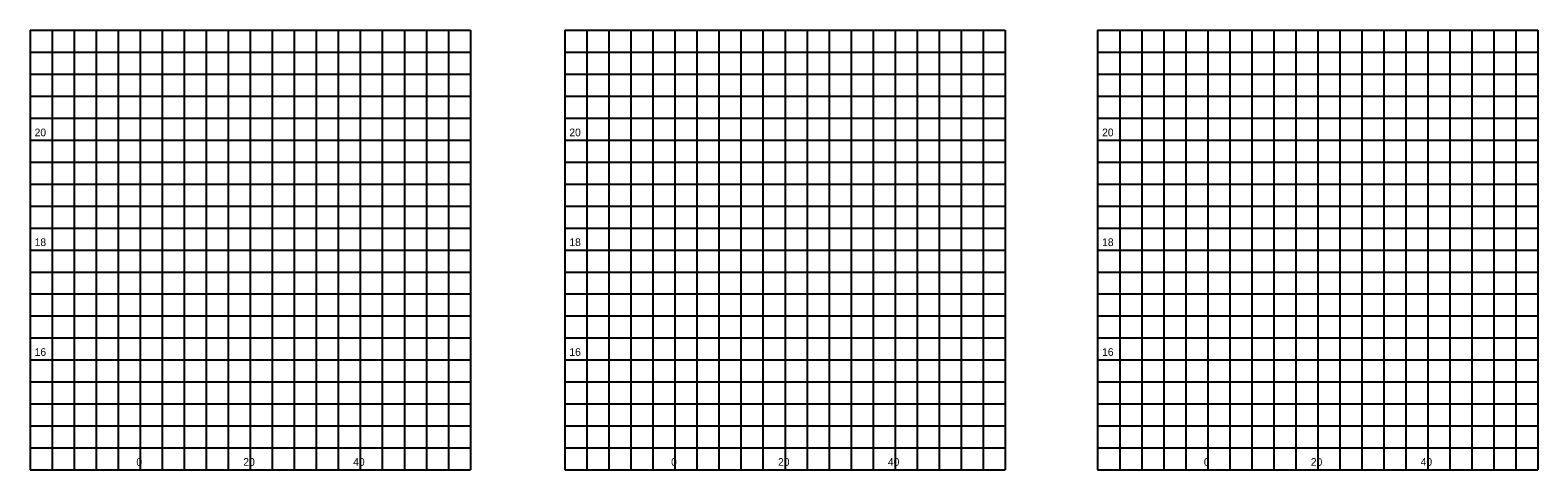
# Model space of a CAD drawing. Extents: x 127723 to 128378, y 21426 to 23736.
# Drawn here: x 127739.5 to 128013.5, y 21910.9 to 21990.9 of the extents above; entities that cross this region are included whole.
import ezdxf

# ---------------------------------------------------------------- set-up
doc = ezdxf.new("R2010")
doc.units = 0
for name, color, linetype in [('GroundCover', 7, 'Continuous'), ('Miscellaneous0', 7, 'Continuous'), ('SheetBorder_dp', 7, 'Continuous')]:
    doc.layers.add(name, color=color, linetype=linetype)

msp = doc.modelspace()

# ---------------------------------------------------------------- linework, layer by layer
at = {"layer": 'Miscellaneous0'}
for p, q in [((127743.54, 21990.89), (127743.54, 21910.89)), ((127747.54, 21990.89), (127747.54, 21910.89)), ((127751.54, 21990.89), (127751.54, 21910.89)), ((127755.54, 21990.89), (127755.54, 21910.89)), ((127763.54, 21990.89), (127763.54, 21910.89)), ((127767.54, 21990.89), (127767.54, 21910.89)), ((127771.54, 21990.89), (127771.54, 21910.89)), ((127775.54, 21990.89), (127775.54, 21910.89)), ((127783.54, 21990.89), (127783.54, 21910.89)), ((127787.54, 21990.89), (127787.54, 21910.89)), ((127791.54, 21990.89), (127791.54, 21910.89)), ((127795.54, 21990.89), (127795.54, 21910.89)), ((127803.54, 21990.89), (127803.54, 21910.89)), ((127807.54, 21990.89), (127807.54, 21910.89)), ((127811.54, 21990.89), (127811.54, 21910.89)), ((127815.54, 21990.89), (127815.54, 21910.89)), ((127840.72, 21990.89), (127840.72, 21910.89)), ((127844.72, 21990.89), (127844.72, 21910.89)), ((127848.72, 21990.89), (127848.72, 21910.89)), ((127852.72, 21990.89), (127852.72, 21910.89)), ((127860.72, 21990.89), (127860.72, 21910.89)), ((127864.72, 21990.89), (127864.72, 21910.89)), ((127868.72, 21990.89), (127868.72, 21910.89)), ((127872.72, 21990.89), (127872.72, 21910.89)), ((127880.72, 21990.89), (127880.72, 21910.89)), ((127884.72, 21990.89), (127884.72, 21910.89)), ((127888.72, 21990.89), (127888.72, 21910.89)), ((127892.72, 21990.89), (127892.72, 21910.89)), ((127900.72, 21990.89), (127900.72, 21910.89)), ((127904.72, 21990.89), (127904.72, 21910.89)), ((127908.72, 21990.89), (127908.72, 21910.89)), ((127912.72, 21990.89), (127912.72, 21910.89)), ((127937.54, 21990.89), (127937.54, 21910.89)), ((127941.54, 21990.89), (127941.54, 21910.89)), ((127945.54, 21990.89), (127945.54, 21910.89)), ((127949.54, 21990.89), (127949.54, 21910.89)), ((127957.54, 21990.89), (127957.54, 21910.89)), ((127961.54, 21990.89), (127961.54, 21910.89)), ((127965.54, 21990.89), (127965.54, 21910.89)), ((127969.54, 21990.89), (127969.54, 21910.89)), ((127977.54, 21990.89), (127977.54, 21910.89)), ((127981.54, 21990.89), (127981.54, 21910.89)), ((127985.54, 21990.89), (127985.54, 21910.89)), ((127989.54, 21990.89), (127989.54, 21910.89)), ((127997.54, 21990.89), (127997.54, 21910.89)), ((128001.54, 21990.89), (128001.54, 21910.89)), ((128005.54, 21990.89), (128005.54, 21910.89)), ((128009.54, 21990.89), (128009.54, 21910.89)), ((127739.54, 21986.89), (127819.54, 21986.89)), ((127836.72, 21986.89), (127916.72, 21986.89)), ((127933.54, 21986.89), (128013.54, 21986.89)), ((127739.54, 21982.89), (127819.54, 21982.89)), ((127836.72, 21982.89), (127916.72, 21982.89)), ((127933.54, 21982.89), (128013.54, 21982.89)), ((127739.54, 21978.89), (127819.54, 21978.89)), ((127836.72, 21978.89), (127916.72, 21978.89)), ((127933.54, 21978.89), (128013.54, 21978.89)), ((127739.54, 21974.89), (127819.54, 21974.89)), ((127836.72, 21974.89), (127916.72, 21974.89)), ((127933.54, 21974.89), (128013.54, 21974.89)), ((127739.54, 21966.89), (127819.54, 21966.89)), ((127836.72, 21966.89), (127916.72, 21966.89)), ((127933.54, 21966.89), (128013.54, 21966.89)), ((127739.54, 21962.89), (127819.54, 21962.89)), ((127836.72, 21962.89), (127916.72, 21962.89)), ((127933.54, 21962.89), (128013.54, 21962.89)), ((127739.54, 21958.89), (127819.54, 21958.89)), ((127836.72, 21958.89), (127916.72, 21958.89)), ((127933.54, 21958.89), (128013.54, 21958.89)), ((127739.54, 21954.89), (127819.54, 21954.89)), ((127836.72, 21954.89), (127916.72, 21954.89)), ((127933.54, 21954.89), (128013.54, 21954.89)), ((127739.54, 21946.89), (127819.54, 21946.89)), ((127836.72, 21946.89), (127916.72, 21946.89)), ((127933.54, 21946.89), (128013.54, 21946.89)), ((127739.54, 21942.89), (127819.54, 21942.89)), ((127836.72, 21942.89), (127916.72, 21942.89)), ((127933.54, 21942.89), (128013.54, 21942.89)), ((127739.54, 21938.89), (127819.54, 21938.89)), ((127836.72, 21938.89), (127916.72, 21938.89)), ((127933.54, 21938.89), (128013.54, 21938.89)), ((127739.54, 21934.89), (127819.54, 21934.89)), ((127836.72, 21934.89), (127916.72, 21934.89)), ((127933.54, 21934.89), (128013.54, 21934.89)), ((127739.54, 21926.89), (127819.54, 21926.89)), ((127836.72, 21926.89), (127916.72, 21926.89)), ((127933.54, 21926.89), (128013.54, 21926.89)), ((127739.54, 21922.89), (127819.54, 21922.89)), ((127836.72, 21922.89), (127916.72, 21922.89)), ((127933.54, 21922.89), (128013.54, 21922.89)), ((127739.54, 21918.89), (127819.54, 21918.89)), ((127836.72, 21918.89), (127916.72, 21918.89)), ((127933.54, 21918.89), (128013.54, 21918.89)), ((127739.54, 21914.89), (127819.54, 21914.89)), ((127836.72, 21914.89), (127916.72, 21914.89)), ((127933.54, 21914.89), (128013.54, 21914.89))]:
    msp.add_line(p, q, dxfattribs=at)
at = {"layer": 'SheetBorder_dp'}
for p, q in [((127739.54, 21990.89), (127819.54, 21990.89)), ((127739.54, 21990.89), (127739.54, 21910.89)), ((127759.54, 21990.89), (127759.54, 21930.89)), ((127759.54, 21990.89), (127759.54, 21910.89)), ((127779.54, 21990.89), (127779.54, 21910.89)), ((127799.54, 21990.89), (127799.54, 21910.89)), ((127819.54, 21990.89), (127819.54, 21910.89)), ((127836.72, 21990.89), (127916.72, 21990.89)), ((127836.72, 21990.89), (127836.72, 21910.89)), ((127856.72, 21990.89), (127856.72, 21930.89)), ((127856.72, 21990.89), (127856.72, 21910.89)), ((127876.72, 21990.89), (127876.72, 21910.89)), ((127896.72, 21990.89), (127896.72, 21910.89)), ((127916.72, 21990.89), (127916.72, 21910.89)), ((127933.54, 21990.89), (128013.54, 21990.89)), ((127933.54, 21990.89), (127933.54, 21910.89)), ((127953.54, 21990.89), (127953.54, 21930.89)), ((127953.54, 21990.89), (127953.54, 21910.89)), ((127973.54, 21990.89), (127973.54, 21910.89)), ((127993.54, 21990.89), (127993.54, 21910.89)), ((128013.54, 21990.89), (128013.54, 21910.89)), ((127739.54, 21970.89), (127819.54, 21970.89)), ((127836.72, 21970.89), (127916.72, 21970.89)), ((127933.54, 21970.89), (128013.54, 21970.89)), ((127739.54, 21950.89), (127819.54, 21950.89)), ((127836.72, 21950.89), (127916.72, 21950.89)), ((127933.54, 21950.89), (128013.54, 21950.89)), ((127739.54, 21930.89), (127819.54, 21930.89)), ((127739.54, 21930.89), (127819.54, 21930.89)), ((127836.72, 21930.89), (127916.72, 21930.89)), ((127836.72, 21930.89), (127916.72, 21930.89)), ((127933.54, 21930.89), (128013.54, 21930.89)), ((127933.54, 21930.89), (128013.54, 21930.89)), ((127739.54, 21910.89), (127819.54, 21910.89)), ((127836.72, 21910.89), (127916.72, 21910.89)), ((127933.54, 21910.89), (128013.54, 21910.89))]:
    msp.add_line(p, q, dxfattribs=at)

# ---------------------------------------------------------------- texts
at = {"layer": 'GroundCover'}
for s, p in [('20', (127740.35, 21971.58)), ('20', (127837.53, 21971.58)), ('20', (127934.35, 21971.58)), ('18', (127740.35, 21951.61)), ('18', (127837.53, 21951.61)), ('18', (127934.35, 21951.61)), ('16', (127740.35, 21931.63)), ('16', (127837.53, 21931.63)), ('16', (127934.35, 21931.63)), ('0', (127758.84, 21911.63)), ('20', (127778.28, 21911.63)), ('40', (127798.24, 21911.63)), ('0', (127856.02, 21911.63)), ('20', (127875.46, 21911.63)), ('40', (127895.42, 21911.63)), ('0', (127952.84, 21911.63)), ('20', (127972.28, 21911.63)), ('40', (127992.24, 21911.63))]:
    msp.add_text(s, height=1.4, dxfattribs=at).set_placement(p)

doc.saveas('drawing.dxf')
